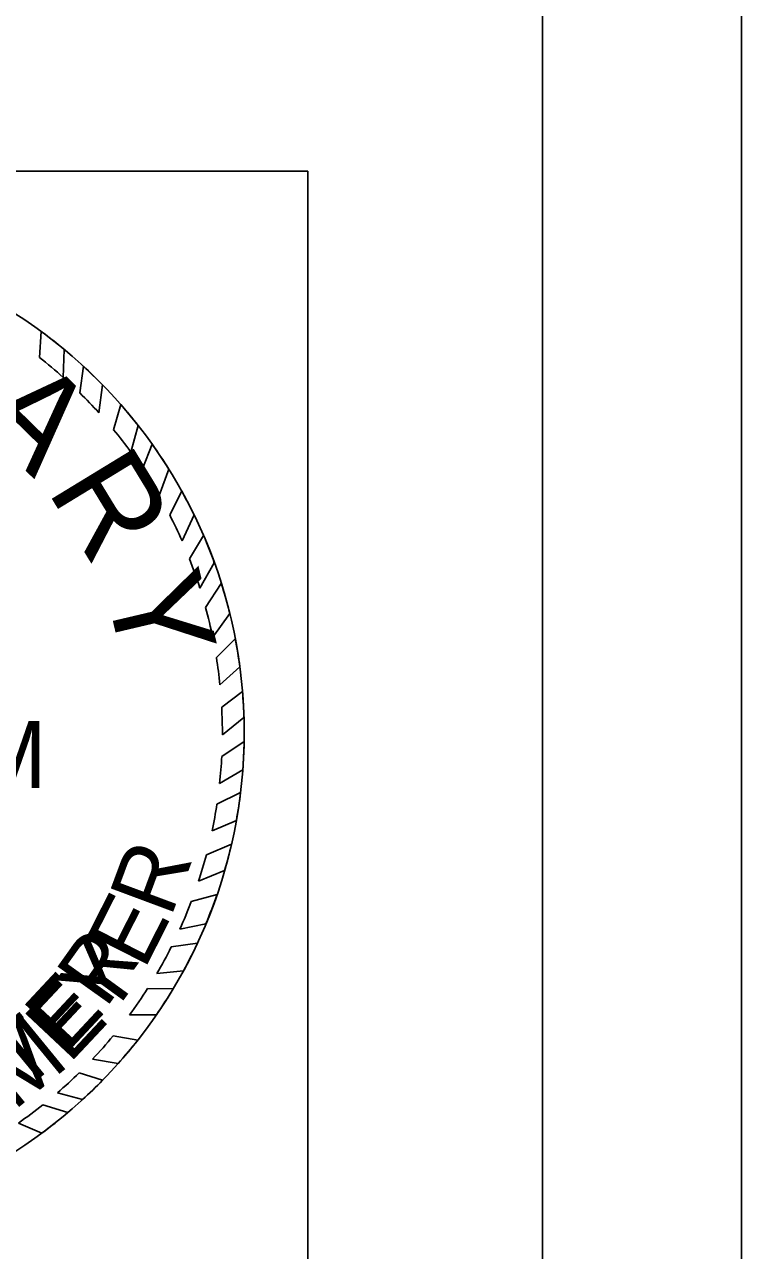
# Model space of a CAD drawing. Extents: x -0.3 to 2.65, y 0 to 1.9.
# Drawn here: x 1.3416 to 1.4167, y 0.0906 to 0.2189 of the extents above; entities that cross this region are included whole.
import ezdxf

# ---------------------------------------------------------------- set-up
doc = ezdxf.new("R2010")
doc.units = 0
for name, color, linetype in [('Level 50', 7, 'Continuous'), ('Level 51', 7, 'Continuous'), ('Level 53', 7, 'Continuous'), ('Level 55', 7, 'Continuous'), ('Level 56', 7, 'Continuous'), ('SHET_Border-Lines', 7, 'Continuous')]:
    doc.layers.add(name, color=color, linetype=linetype)

msp = doc.modelspace()

# ---------------------------------------------------------------- linework, layer by layer
at = {"layer": 'Level 50'}
msp.add_circle((1.3125000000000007, 0.14479166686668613), 0.05208333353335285, dxfattribs=at)
at = {"layer": 'Level 51'}
for p, q in [((1.3431312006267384, 0.18405361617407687), (1.3433223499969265, 0.18677566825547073)), ((1.345625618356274, 0.18197317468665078), (1.3457347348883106, 0.1848931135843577)), ((1.3473716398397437, 0.18034078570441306), (1.3477586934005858, 0.1831257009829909)), ((1.3493777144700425, 0.1782551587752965), (1.349749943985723, 0.181193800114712)), ((1.3509076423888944, 0.17648747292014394), (1.351669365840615, 0.17911999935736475)), ((1.3527177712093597, 0.17415664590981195), (1.3534723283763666, 0.1769466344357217)), ((1.35394615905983, 0.17239577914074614), (1.3549390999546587, 0.17498432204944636)), ((1.355667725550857, 0.16961743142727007), (1.356687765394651, 0.17236185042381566)), ((1.3567821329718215, 0.16757024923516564), (1.3580476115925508, 0.17005208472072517)), ((1.358071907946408, 0.16486583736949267), (1.3593364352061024, 0.16757372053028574)), ((1.358856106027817, 0.16298184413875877), (1.36033068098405, 0.16540475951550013)), ((1.3599451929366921, 0.1599153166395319), (1.3614566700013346, 0.16256575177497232)), ((1.3605469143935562, 0.1578784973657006), (1.3621878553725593, 0.16040546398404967)), ((1.361289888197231, 0.15475750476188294), (1.3630707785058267, 0.1572524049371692)), ((1.361675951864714, 0.15263366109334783), (1.3636501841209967, 0.1546065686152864)), ((1.362045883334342, 0.14978932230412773), (1.3641275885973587, 0.15166667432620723)), ((1.3622261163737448, 0.1474533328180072), (1.36440619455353, 0.1490835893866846)), ((1.3622967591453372, 0.14455951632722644), (1.364559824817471, 0.14635636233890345)), ((1.3622347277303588, 0.14229607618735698), (1.3645747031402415, 0.14384355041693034)), ((1.3620119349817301, 0.13946818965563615), (1.3644377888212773, 0.14090068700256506)), ((1.3617300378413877, 0.13729670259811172), (1.3642048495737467, 0.13852411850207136)), ((1.3612231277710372, 0.134504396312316), (1.363765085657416, 0.13559576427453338)), ((1.3606212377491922, 0.13198082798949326), (1.3632555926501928, 0.1331064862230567)), ((1.35979979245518, 0.12921923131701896), (1.3625386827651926, 0.1303416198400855)), ((1.3590474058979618, 0.12709674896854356), (1.3617437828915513, 0.12782925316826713)), ((1.357850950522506, 0.12422318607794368), (1.3605781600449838, 0.12476258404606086)), ((1.3569513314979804, 0.12234505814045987), (1.3596778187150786, 0.1227252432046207)), ((1.3554309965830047, 0.11955873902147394), (1.3582298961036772, 0.11986276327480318)), ((1.3544708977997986, 0.11799213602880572), (1.357138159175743, 0.11795683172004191)), ((1.3525738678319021, 0.1152306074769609), (1.3553925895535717, 0.11524679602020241)), ((1.3508534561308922, 0.11303031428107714), (1.353432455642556, 0.1125859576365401)), ((1.3487131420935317, 0.11061010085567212), (1.3513780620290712, 0.11013376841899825)), ((1.3472891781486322, 0.10916184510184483), (1.3497523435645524, 0.10839198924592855)), ((1.345021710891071, 0.10708080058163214), (1.34765465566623, 0.10636220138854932)), ((1.3435092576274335, 0.10582761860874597), (1.3461231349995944, 0.10501531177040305)), ((1.3409364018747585, 0.10391206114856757), (1.3433867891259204, 0.10285504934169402))]:
    msp.add_line(p, q, dxfattribs=at)
for radius, start, end in [(0.05208333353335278, 50.34919923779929, 53.715927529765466), (0.04979730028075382, 48.301629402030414, 52.0395271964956), (0.05208333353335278, 44.34049610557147, 47.392920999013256), (0.04979730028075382, 42.221157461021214, 45.55119386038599), (0.05208333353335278, 38.12472275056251, 41.2315730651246), (0.04979730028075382, 36.135025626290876, 39.53106373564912), (0.05208333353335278, 31.96138013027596, 35.42937309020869), (0.04979730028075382, 29.903213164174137, 33.66454441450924), (0.05208333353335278, 25.939091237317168, 29.012473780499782), (0.04979730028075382, 23.77322286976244, 27.221139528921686), (0.05208333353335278, 19.953806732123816, 23.314091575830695), (0.04979730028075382, 17.68022309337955, 21.42508660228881), (0.05208333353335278, 13.842052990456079, 17.444684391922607), (0.04979730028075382, 11.544448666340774, 15.236388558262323), (0.05208333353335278, 7.585188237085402, 10.862114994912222), (0.04979730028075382, 5.7598993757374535, 9.06055796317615), (0.05208333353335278, 1.7215475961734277, 4.7268136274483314), (0.04979730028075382, 359.7328912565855, 3.0639197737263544), (0.05208333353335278, 355.71562332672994, 358.956939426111), (0.04979730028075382, 353.86318650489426, 357.12741991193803), (0.05208333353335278, 349.83046937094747, 353.08845194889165), (0.04979730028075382, 348.07782395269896, 351.34354893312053), (0.05208333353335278, 343.8924710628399, 347.03501976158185), (0.04979730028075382, 341.7769864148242, 345.0924752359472), (0.04979730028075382, 335.60379596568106, 339.1857838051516), (0.05208333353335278, 337.3836727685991, 340.99332282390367), (0.04979730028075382, 329.55488416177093, 333.20757358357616), (0.05208333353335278, 331.4037138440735, 334.933154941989), (0.04979730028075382, 323.58513069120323, 327.44068976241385), (0.05208333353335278, 325.4405170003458, 328.9872482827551), (0.04979730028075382, 316.6530849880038, 320.3710862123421), (0.05208333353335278, 318.2845512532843, 321.8042854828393), (0.04979730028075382, 310.7743619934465, 314.31605044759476), (0.05208333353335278, 312.45177291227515, 315.66328088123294), (0.04979730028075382, 304.8229923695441, 308.51427595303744), (0.05208333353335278, 306.37206251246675, 310.20798964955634)]:
    msp.add_arc((1.3125000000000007, 0.14479166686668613), radius, start, end, dxfattribs=at)
at = {"layer": 'Level 56'}
msp.add_lwpolyline([(1.3712499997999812, 0.2035416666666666), (1.2520833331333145, 0.2035416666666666), (1.2520833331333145, 0.08437499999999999), (1.3712499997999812, 0.08437499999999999)], close=True, dxfattribs=at)
at = {"layer": 'SHET_Border-Lines'}
for points in [[(0, 0), (1.416666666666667, 0), (1.416666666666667, 0.9166666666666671), (0, 0.9166666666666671)], [(0.02083333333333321, 0.02083333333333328), (1.3958333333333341, 0.02083333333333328), (1.3958333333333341, 0.8958333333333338), (0.02083333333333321, 0.8958333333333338)]]:
    msp.add_lwpolyline(points, close=True, dxfattribs=at)

# ---------------------------------------------------------------- texts
at = {"layer": 'Level 50'}
for s, height, rotation, p in [('A', 0.010056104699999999, 315.65789090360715, (1.3362148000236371, 0.17755060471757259)), ('R', 0.010056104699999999, 301.38306156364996, (1.3438568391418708, 0.17020900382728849)), ('Y', 0.010056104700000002, 283.25926303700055, (1.3499420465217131, 0.160228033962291))]:
    msp.add_text(s, height=height, rotation=rotation, dxfattribs=at).set_placement(p)
msp.add_text('PICKERING FIRM', height=0.006983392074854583, dxfattribs=at).set_placement((1.2670979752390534, 0.13899943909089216))
at = {"layer": 'Level 53'}
for s, height, rotation, p in [('R', 0.006704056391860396, 54.50309997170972, (1.350066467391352, 0.11580297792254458)), ('E', 0.006704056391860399, 46.96130660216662, (1.3460238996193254, 0.11121650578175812)), ('T', 0.006704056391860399, 39.41937898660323, (1.3412284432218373, 0.10702580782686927))]:
    msp.add_text(s, height=height, rotation=rotation, dxfattribs=at).set_placement(p)
at = {"layer": 'Level 55'}
for s, height, rotation, p in [('R', 0.006983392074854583, 69.57000985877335, (1.3568870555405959, 0.12531919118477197)), ('E', 0.00698339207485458, 63.09839547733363, (1.3541015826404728, 0.11983535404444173)), ('Y', 0.006983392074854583, 53.99864225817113, (1.3503639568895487, 0.11458068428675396)), ('E', 0.006983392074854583, 46.80937910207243, (1.346234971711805, 0.11002725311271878)), ('M', 0.00698339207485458, 39.30004668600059, (1.3404223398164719, 0.10511583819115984))]:
    msp.add_text(s, height=height, rotation=rotation, dxfattribs=at).set_placement(p)

doc.saveas('drawing.dxf')
